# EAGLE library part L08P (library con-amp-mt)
AMP MT CONNECTOR
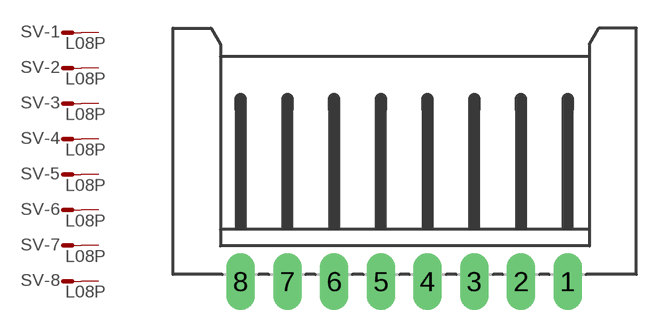
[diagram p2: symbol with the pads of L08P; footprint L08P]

Designator prefix SV; gates -1=M -2=M -3=M -4=M -5=M -6=M -7=M -8=M

## L08P (OC_FARNELL: unknown; OC_NEWARK: unknown)  [L08P]
1  -1:S  pas
2  -2:S  pas
3  -3:S  pas
4  -4:S  pas
5  -5:S  pas
6  -6:S  pas
7  -7:S  pas
8  -8:S  pas

## Footprint L08P (pad centres in mm)
AMP MT CONNECTOR
drill 1.016 long: 1 8.75,-6.25; 2 6.25,-6.25; 3 3.75,-6.25; 4 1.25,-6.25; 5 -1.25,-6.25; 6 -3.75,-6.25; 7 -6.25,-6.25; 8 -8.75,-6.25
